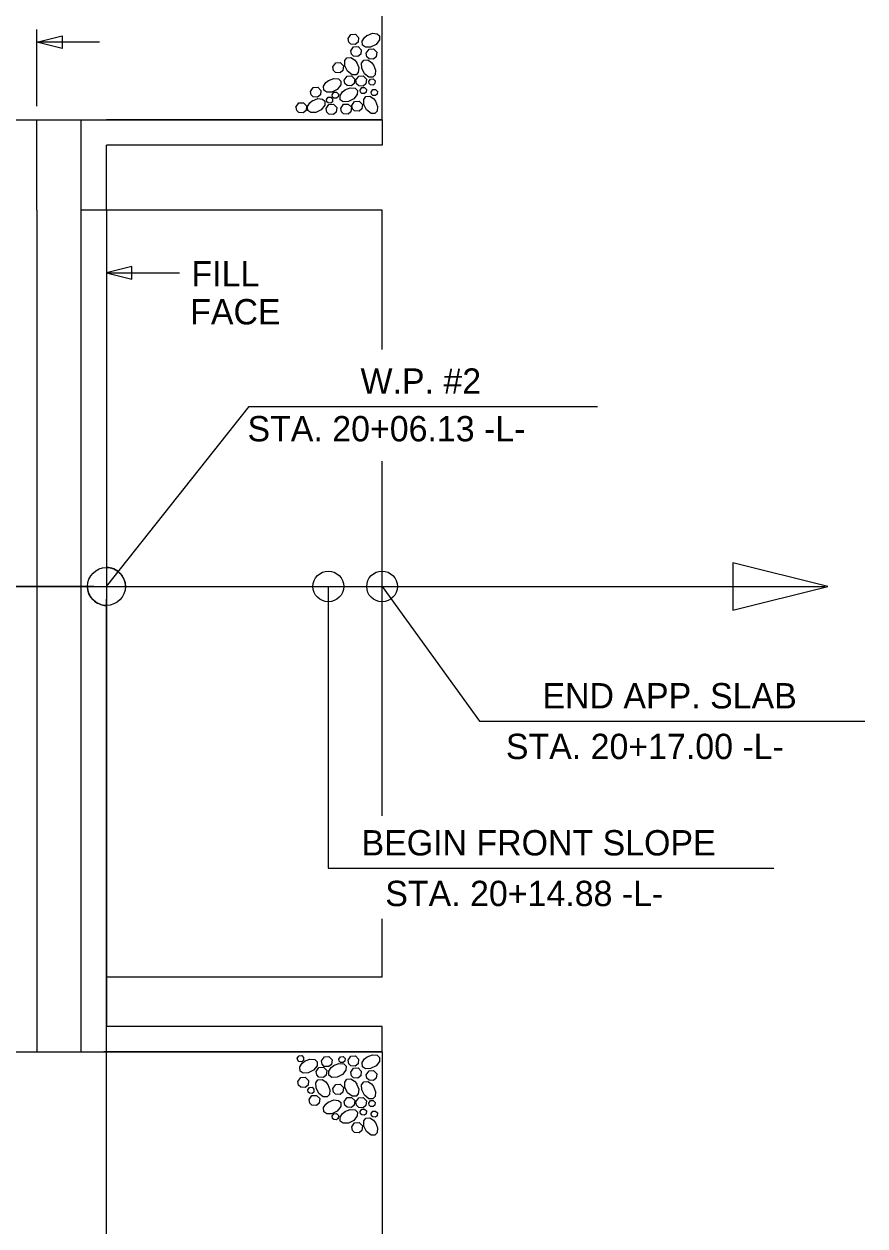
# Model space of a CAD drawing. Extents: x 985 to 1514, y -701 to -21.
# Drawn here: x 1154 to 1187.17, y -184.23 to -136.79 of the extents above; entities that cross this region are included whole.
import ezdxf

# ---------------------------------------------------------------- set-up
doc = ezdxf.new("R2010")
doc.units = 0
for name, color, linetype in [('Arrowhead Terminators CELL', 7, 'Continuous'), ('Auto Dimensioning', 7, 'Continuous'), ('Default', 7, 'Continuous'), ('Dimension Lines', 7, 'Continuous'), ('Mis -L- Lines', 7, 'Continuous'), ('Mis Object Lines', 7, 'Continuous'), ('Mis Object Lines Hidden', 7, 'Continuous'), ('Mis Work Point CELL', 7, 'Continuous'), ('Miscellaneous Lines CELL', 7, 'Continuous'), ('Sub End Bent Cap Lines CELL', 7, 'Continuous'), ('Sup Concrete Girder Lines', 7, 'Continuous'), ('Text', 7, 'Continuous'), ('User Information Notes', 7, 'Continuous')]:
    doc.layers.add(name, color=color, linetype=linetype)

# ---------------------------------------------------------------- blocks, each defined once
blk = doc.blocks.new('AH')
at = {"layer": 'Sub End Bent Cap Lines CELL'}
blk.add_lwpolyline([(0, 0), (-1.25, 0.312), (-1.25, -0.312)], close=True, dxfattribs=at)

msp = doc.modelspace()

# ---------------------------------------------------------------- linework, layer by layer
at = {"layer": 'Arrowhead Terminators CELL'}
for points in [[(1157.252, -146.603), (1158.252, -146.853), (1158.252, -146.353)], [(1185.71, -158.986), (1181.96, -158.048), (1181.96, -159.923)]]:
    msp.add_lwpolyline(points, close=True, dxfattribs=at)
at = {"layer": 'Auto Dimensioning'}
for p, q in [((1156.752, -158.986), (1143.03, -158.986)), ((1157.234, -159.486), (1157.234, -191.32))]:
    msp.add_line(p, q, dxfattribs=at)
at = {"layer": 'Default'}
msp.add_line((1157.142, -177.358), (1167.142, -177.358), dxfattribs=at)
at = {"layer": 'Dimension Lines'}
for p, q in [((1154.502, -140.029), (1154.502, -137.01)), ((1156.983, -137.51), (1154.502, -137.51)), ((1157.252, -146.603), (1160.13, -146.603)), ((1157.252, -158.986), (1162.882, -151.881)), ((1162.882, -151.881), (1176.615, -151.881)), ((1166.002, -158.986), (1166.002, -170.103)), ((1168.122, -158.986), (1171.966, -164.3)), ((1171.966, -164.3), (1187.167, -164.3)), ((1166.002, -170.103), (1183.575, -170.103))]:
    msp.add_line(p, q, dxfattribs=at)
for centre in [(1166.002, -158.986), (1168.122, -158.986)]:
    msp.add_circle(centre, 0.606, dxfattribs=at)
at = {"layer": 'Mis -L- Lines'}
msp.add_line((1058.329, -158.986), (1185.585, -158.986), dxfattribs=at)
at = {"layer": 'Mis Object Lines'}
for p, q in [((1153.502, -140.569), (1168.122, -140.569)), ((1154.502, -144.132), (1154.502, -140.569)), ((1156.252, -177.358), (1156.252, -140.569)), ((1168.122, -140.569), (1168.122, -141.569)), ((1168.122, -141.569), (1157.252, -141.569)), ((1157.252, -144.132), (1157.252, -141.569)), ((1154.502, -144.132), (1154.502, -177.358)), ((1168.122, -144.132), (1156.252, -144.132)), ((1168.122, -149.633), (1168.122, -144.132)), ((1168.122, -168.045), (1168.122, -154.044)), ((1168.122, -174.402), (1168.122, -172.099)), ((1168.122, -174.402), (1157.252, -174.402)), ((1157.252, -174.402), (1157.252, -176.358)), ((1168.122, -176.358), (1157.252, -176.358)), ((1168.122, -177.358), (1168.122, -176.358)), ((1153.502, -177.358), (1168.122, -177.358))]:
    msp.add_line(p, q, dxfattribs=at)
at = {"layer": 'Mis Object Lines Hidden'}
msp.add_line((1157.252, -144.132), (1157.252, -174.965), dxfattribs=at)
at = {"layer": 'Mis Work Point CELL'}
for p, q in [((1157.252, -158.236), (1157.252, -158.986)), ((1156.502, -158.986), (1157.252, -158.986)), ((1157.252, -158.986), (1157.252, -159.736)), ((1157.252, -158.986), (1158.002, -158.986)), ((1158.002, -158.986), (1158.002, -158.986)), ((1157.252, -159.736), (1157.252, -159.736))]:
    msp.add_line(p, q, dxfattribs=at)
msp.add_circle((1157.252, -158.986), 0.75, dxfattribs=at)
for start, end in [(359.997, 89.9989), (180.0011, 270.003)]:
    msp.add_arc((1157.252, -158.986), 0.75, start, end, dxfattribs=at)
at = {"layer": 'Miscellaneous Lines CELL'}
for points in [[(1166.78, -137.366), (1166.892, -137.207), (1167.071, -137.196), (1167.195, -137.325), (1167.177, -137.506), (1167.067, -137.598), (1166.89, -137.585), (1166.807, -137.505), (1166.78, -137.366)], [(1167.532, -137.239), (1167.741, -137.156), (1167.934, -137.172), (1168.025, -137.259), (1168.022, -137.415), (1167.884, -137.593), (1167.669, -137.7), (1167.467, -137.704), (1167.353, -137.623), (1167.342, -137.462), (1167.434, -137.318), (1167.54, -137.233)], [(1166.885, -137.843), (1166.997, -137.684), (1167.176, -137.674), (1167.301, -137.803), (1167.283, -137.983), (1167.172, -138.075), (1166.995, -138.062), (1166.912, -137.982), (1166.885, -137.843)], [(1167.498, -137.941), (1167.61, -137.781), (1167.789, -137.771), (1167.913, -137.9), (1167.895, -138.081), (1167.785, -138.173), (1167.608, -138.16), (1167.525, -138.079), (1167.498, -137.941)], [(1166.181, -138.483), (1166.293, -138.324), (1166.472, -138.313), (1166.596, -138.442), (1166.578, -138.623), (1166.468, -138.715), (1166.291, -138.702), (1166.208, -138.622), (1166.181, -138.483)], [(1167.118, -138.297), (1167.201, -138.507), (1167.185, -138.699), (1167.098, -138.791), (1166.942, -138.788), (1166.764, -138.649), (1166.657, -138.434), (1166.653, -138.232), (1166.734, -138.118), (1166.895, -138.108), (1167.039, -138.2), (1167.124, -138.306)], [(1167.783, -138.399), (1167.866, -138.609), (1167.849, -138.801), (1167.762, -138.893), (1167.606, -138.89), (1167.428, -138.751), (1167.321, -138.536), (1167.317, -138.334), (1167.398, -138.22), (1167.56, -138.209), (1167.704, -138.302), (1167.788, -138.407)], [(1166.004, -139.017), (1166.214, -138.934), (1166.406, -138.951), (1166.498, -139.038), (1166.495, -139.194), (1166.356, -139.371), (1166.142, -139.479), (1165.939, -139.482), (1165.825, -139.401), (1165.815, -139.24), (1165.907, -139.096), (1166.013, -139.012)], [(1166.629, -139.003), (1166.741, -138.843), (1166.92, -138.833), (1167.045, -138.962), (1167.027, -139.143), (1166.916, -139.234), (1166.739, -139.222), (1166.656, -139.141), (1166.629, -139.003)], [(1167.09, -139.009), (1167.202, -138.85), (1167.381, -138.84), (1167.506, -138.969), (1167.488, -139.149), (1167.377, -139.241), (1167.2, -139.228), (1167.117, -139.148), (1167.09, -139.009)], [(1167.6, -139.059), (1167.667, -138.963), (1167.775, -138.957), (1167.849, -139.034), (1167.838, -139.143), (1167.772, -139.198), (1167.666, -139.19), (1167.616, -139.142), (1167.6, -139.059)], [(1165.295, -139.448), (1165.407, -139.289), (1165.586, -139.278), (1165.711, -139.407), (1165.693, -139.588), (1165.582, -139.68), (1165.405, -139.667), (1165.322, -139.587), (1165.295, -139.448)], [(1166.655, -139.392), (1166.864, -139.308), (1167.057, -139.325), (1167.148, -139.412), (1167.145, -139.568), (1167.006, -139.746), (1166.792, -139.853), (1166.59, -139.857), (1166.476, -139.776), (1166.465, -139.615), (1166.557, -139.471), (1166.663, -139.386)], [(1167.253, -139.395), (1167.32, -139.299), (1167.428, -139.293), (1167.502, -139.37), (1167.492, -139.479), (1167.425, -139.534), (1167.319, -139.526), (1167.269, -139.478), (1167.253, -139.395)], [(1167.695, -139.474), (1167.762, -139.378), (1167.869, -139.372), (1167.944, -139.449), (1167.933, -139.558), (1167.867, -139.613), (1167.761, -139.605), (1167.711, -139.557), (1167.695, -139.474)], [(1164.727, -140.064), (1164.84, -139.905), (1165.018, -139.895), (1165.143, -140.024), (1165.125, -140.204), (1165.014, -140.296), (1164.838, -140.283), (1164.755, -140.203), (1164.728, -140.064)], [(1165.374, -139.819), (1165.583, -139.735), (1165.776, -139.752), (1165.867, -139.839), (1165.864, -139.995), (1165.726, -140.173), (1165.511, -140.28), (1165.309, -140.284), (1165.195, -140.203), (1165.184, -140.042), (1165.276, -139.898), (1165.382, -139.813)], [(1165.924, -139.773), (1165.991, -139.677), (1166.099, -139.671), (1166.173, -139.749), (1166.162, -139.857), (1166.096, -139.912), (1165.99, -139.905), (1165.94, -139.856), (1165.924, -139.773)], [(1166.155, -139.579), (1166.222, -139.483), (1166.33, -139.477), (1166.404, -139.554), (1166.394, -139.663), (1166.327, -139.718), (1166.221, -139.71), (1166.171, -139.662), (1166.155, -139.579)], [(1166.929, -140), (1167.041, -139.841), (1167.22, -139.83), (1167.344, -139.959), (1167.326, -140.14), (1167.216, -140.232), (1167.039, -140.219), (1166.956, -140.138), (1166.929, -140)], [(1167.864, -139.829), (1167.947, -140.039), (1167.93, -140.231), (1167.843, -140.323), (1167.687, -140.32), (1167.51, -140.181), (1167.402, -139.966), (1167.399, -139.764), (1167.48, -139.65), (1167.641, -139.639), (1167.785, -139.732), (1167.869, -139.838)], [(1165.917, -140.123), (1166.029, -139.964), (1166.207, -139.954), (1166.332, -140.083), (1166.314, -140.263), (1166.203, -140.355), (1166.027, -140.343), (1165.944, -140.262), (1165.917, -140.123)], [(1166.495, -140.117), (1166.607, -139.957), (1166.786, -139.947), (1166.91, -140.076), (1166.892, -140.257), (1166.781, -140.349), (1166.605, -140.336), (1166.522, -140.255), (1166.495, -140.117)], [(1164.778, -177.605), (1164.846, -177.509), (1164.953, -177.503), (1165.028, -177.581), (1165.017, -177.689), (1164.951, -177.744), (1164.845, -177.736), (1164.795, -177.688), (1164.779, -177.605)], [(1164.778, -177.605), (1164.846, -177.509), (1164.953, -177.503), (1165.028, -177.581), (1165.017, -177.689), (1164.951, -177.744), (1164.845, -177.736), (1164.795, -177.688), (1164.779, -177.605)], [(1165.069, -177.728), (1165.278, -177.645), (1165.471, -177.661), (1165.562, -177.748), (1165.56, -177.904), (1165.421, -178.082), (1165.206, -178.189), (1165.004, -178.193), (1164.89, -178.112), (1164.879, -177.951), (1164.971, -177.807), (1165.077, -177.722)], [(1165.069, -177.728), (1165.278, -177.645), (1165.471, -177.661), (1165.562, -177.748), (1165.56, -177.904), (1165.421, -178.082), (1165.206, -178.189), (1165.004, -178.193), (1164.89, -178.112), (1164.879, -177.951), (1164.971, -177.807), (1165.077, -177.722)], [(1165.733, -177.707), (1165.845, -177.548), (1166.024, -177.538), (1166.148, -177.667), (1166.13, -177.847), (1166.019, -177.939), (1165.843, -177.926), (1165.76, -177.846), (1165.733, -177.707)], [(1165.733, -177.707), (1165.845, -177.548), (1166.024, -177.538), (1166.148, -177.667), (1166.13, -177.847), (1166.019, -177.939), (1165.843, -177.926), (1165.76, -177.846), (1165.733, -177.707)], [(1166.208, -177.897), (1166.417, -177.814), (1166.61, -177.831), (1166.701, -177.918), (1166.698, -178.074), (1166.559, -178.252), (1166.345, -178.359), (1166.142, -178.362), (1166.029, -178.281), (1166.018, -178.12), (1166.11, -177.976), (1166.216, -177.892)], [(1166.208, -177.897), (1166.417, -177.814), (1166.61, -177.831), (1166.701, -177.918), (1166.698, -178.074), (1166.559, -178.252), (1166.345, -178.359), (1166.142, -178.362), (1166.029, -178.281), (1166.018, -178.12), (1166.11, -177.976), (1166.216, -177.892)], [(1166.412, -177.642), (1166.48, -177.546), (1166.587, -177.54), (1166.662, -177.617), (1166.651, -177.726), (1166.585, -177.781), (1166.479, -177.773), (1166.429, -177.725), (1166.413, -177.642)], [(1166.412, -177.642), (1166.48, -177.546), (1166.587, -177.54), (1166.662, -177.617), (1166.651, -177.726), (1166.585, -177.781), (1166.479, -177.773), (1166.429, -177.725), (1166.413, -177.642)], [(1166.78, -177.683), (1166.892, -177.524), (1167.071, -177.513), (1167.195, -177.642), (1167.177, -177.823), (1167.066, -177.915), (1166.89, -177.902), (1166.807, -177.822), (1166.78, -177.683)], [(1166.78, -177.683), (1166.892, -177.524), (1167.071, -177.513), (1167.195, -177.642), (1167.177, -177.823), (1167.066, -177.915), (1166.89, -177.902), (1166.807, -177.822), (1166.78, -177.683)], [(1167.532, -177.556), (1167.741, -177.473), (1167.934, -177.489), (1168.025, -177.576), (1168.022, -177.732), (1167.883, -177.91), (1167.669, -178.017), (1167.467, -178.021), (1167.353, -177.94), (1167.342, -177.779), (1167.434, -177.635), (1167.54, -177.55)], [(1167.532, -177.556), (1167.741, -177.473), (1167.934, -177.489), (1168.025, -177.576), (1168.022, -177.732), (1167.883, -177.91), (1167.669, -178.017), (1167.467, -178.021), (1167.353, -177.94), (1167.342, -177.779), (1167.434, -177.635), (1167.54, -177.55)], [(1164.803, -178.529), (1164.915, -178.369), (1165.094, -178.359), (1165.219, -178.488), (1165.201, -178.669), (1165.09, -178.761), (1164.913, -178.748), (1164.83, -178.667), (1164.803, -178.529)], [(1164.803, -178.529), (1164.915, -178.369), (1165.094, -178.359), (1165.219, -178.488), (1165.201, -178.669), (1165.09, -178.761), (1164.913, -178.748), (1164.83, -178.667), (1164.803, -178.529)], [(1165.522, -178.129), (1165.634, -177.97), (1165.813, -177.959), (1165.937, -178.088), (1165.919, -178.269), (1165.809, -178.361), (1165.632, -178.348), (1165.549, -178.267), (1165.522, -178.129)], [(1165.522, -178.129), (1165.634, -177.97), (1165.813, -177.959), (1165.937, -178.088), (1165.919, -178.269), (1165.809, -178.361), (1165.632, -178.348), (1165.549, -178.267), (1165.522, -178.129)], [(1166.885, -178.16), (1166.997, -178.001), (1167.176, -177.991), (1167.3, -178.12), (1167.282, -178.3), (1167.172, -178.392), (1166.995, -178.379), (1166.912, -178.299), (1166.885, -178.16)], [(1166.885, -178.16), (1166.997, -178.001), (1167.176, -177.991), (1167.3, -178.12), (1167.282, -178.3), (1167.172, -178.392), (1166.995, -178.379), (1166.912, -178.299), (1166.885, -178.16)], [(1167.498, -178.258), (1167.61, -178.098), (1167.789, -178.088), (1167.913, -178.217), (1167.895, -178.398), (1167.785, -178.49), (1167.608, -178.477), (1167.525, -178.396), (1167.498, -178.258)], [(1167.498, -178.258), (1167.61, -178.098), (1167.789, -178.088), (1167.913, -178.217), (1167.895, -178.398), (1167.785, -178.49), (1167.608, -178.477), (1167.525, -178.396), (1167.498, -178.258)], [(1165.188, -178.855), (1165.256, -178.76), (1165.363, -178.754), (1165.437, -178.831), (1165.427, -178.939), (1165.36, -178.995), (1165.254, -178.987), (1165.205, -178.939), (1165.188, -178.855)], [(1165.188, -178.855), (1165.256, -178.76), (1165.363, -178.754), (1165.437, -178.831), (1165.427, -178.939), (1165.36, -178.995), (1165.254, -178.987), (1165.205, -178.939), (1165.188, -178.855)], [(1165.98, -178.641), (1166.063, -178.851), (1166.046, -179.044), (1165.959, -179.135), (1165.803, -179.132), (1165.625, -178.993), (1165.518, -178.779), (1165.514, -178.576), (1165.595, -178.462), (1165.756, -178.452), (1165.9, -178.544), (1165.985, -178.65)], [(1165.98, -178.641), (1166.063, -178.851), (1166.046, -179.044), (1165.959, -179.135), (1165.803, -179.132), (1165.625, -178.993), (1165.518, -178.779), (1165.514, -178.576), (1165.595, -178.462), (1165.756, -178.452), (1165.9, -178.544), (1165.985, -178.65)], [(1166.181, -178.8), (1166.293, -178.641), (1166.472, -178.63), (1166.596, -178.759), (1166.578, -178.94), (1166.468, -179.032), (1166.291, -179.019), (1166.208, -178.939), (1166.181, -178.8)], [(1166.181, -178.8), (1166.293, -178.641), (1166.472, -178.63), (1166.596, -178.759), (1166.578, -178.94), (1166.468, -179.032), (1166.291, -179.019), (1166.208, -178.939), (1166.181, -178.8)], [(1167.118, -178.614), (1167.201, -178.824), (1167.185, -179.016), (1167.098, -179.108), (1166.942, -179.105), (1166.764, -178.966), (1166.657, -178.752), (1166.653, -178.549), (1166.734, -178.435), (1166.895, -178.425), (1167.039, -178.517), (1167.124, -178.623)], [(1167.118, -178.614), (1167.201, -178.824), (1167.185, -179.016), (1167.098, -179.108), (1166.942, -179.105), (1166.764, -178.966), (1166.657, -178.752), (1166.653, -178.549), (1166.734, -178.435), (1166.895, -178.425), (1167.039, -178.517), (1167.124, -178.623)], [(1167.783, -178.716), (1167.866, -178.926), (1167.849, -179.118), (1167.762, -179.21), (1167.606, -179.207), (1167.428, -179.068), (1167.321, -178.853), (1167.317, -178.651), (1167.398, -178.537), (1167.559, -178.526), (1167.704, -178.619), (1167.788, -178.724)], [(1167.783, -178.716), (1167.866, -178.926), (1167.849, -179.118), (1167.762, -179.21), (1167.606, -179.207), (1167.428, -179.068), (1167.321, -178.853), (1167.317, -178.651), (1167.398, -178.537), (1167.559, -178.526), (1167.704, -178.619), (1167.788, -178.724)], [(1165.245, -179.241), (1165.357, -179.081), (1165.536, -179.071), (1165.661, -179.2), (1165.643, -179.381), (1165.532, -179.473), (1165.356, -179.46), (1165.272, -179.379), (1165.245, -179.241)], [(1165.245, -179.241), (1165.357, -179.081), (1165.536, -179.071), (1165.661, -179.2), (1165.643, -179.381), (1165.532, -179.473), (1165.356, -179.46), (1165.272, -179.379), (1165.245, -179.241)], [(1166.004, -179.334), (1166.214, -179.251), (1166.406, -179.268), (1166.498, -179.355), (1166.495, -179.511), (1166.356, -179.689), (1166.141, -179.796), (1165.939, -179.799), (1165.825, -179.718), (1165.814, -179.557), (1165.907, -179.413), (1166.013, -179.329)], [(1166.004, -179.334), (1166.214, -179.251), (1166.406, -179.268), (1166.498, -179.355), (1166.495, -179.511), (1166.356, -179.689), (1166.141, -179.796), (1165.939, -179.799), (1165.825, -179.718), (1165.814, -179.557), (1165.907, -179.413), (1166.013, -179.329)], [(1166.629, -179.32), (1166.741, -179.16), (1166.92, -179.15), (1167.045, -179.279), (1167.027, -179.46), (1166.916, -179.552), (1166.739, -179.539), (1166.656, -179.458), (1166.629, -179.32)], [(1166.629, -179.32), (1166.741, -179.16), (1166.92, -179.15), (1167.045, -179.279), (1167.027, -179.46), (1166.916, -179.552), (1166.739, -179.539), (1166.656, -179.458), (1166.629, -179.32)], [(1167.09, -179.326), (1167.202, -179.167), (1167.381, -179.157), (1167.505, -179.286), (1167.487, -179.466), (1167.377, -179.558), (1167.2, -179.545), (1167.117, -179.465), (1167.09, -179.326)], [(1167.09, -179.326), (1167.202, -179.167), (1167.381, -179.157), (1167.505, -179.286), (1167.487, -179.466), (1167.377, -179.558), (1167.2, -179.545), (1167.117, -179.465), (1167.09, -179.326)], [(1167.6, -179.376), (1167.667, -179.28), (1167.775, -179.274), (1167.849, -179.351), (1167.838, -179.46), (1167.772, -179.515), (1167.666, -179.507), (1167.616, -179.459), (1167.6, -179.376)], [(1167.6, -179.376), (1167.667, -179.28), (1167.775, -179.274), (1167.849, -179.351), (1167.838, -179.46), (1167.772, -179.515), (1167.666, -179.507), (1167.616, -179.459), (1167.6, -179.376)], [(1166.655, -179.709), (1166.864, -179.626), (1167.057, -179.642), (1167.148, -179.729), (1167.145, -179.885), (1167.006, -180.063), (1166.792, -180.17), (1166.589, -180.174), (1166.476, -180.093), (1166.465, -179.932), (1166.557, -179.788), (1166.663, -179.703)], [(1166.655, -179.709), (1166.864, -179.626), (1167.057, -179.642), (1167.148, -179.729), (1167.145, -179.885), (1167.006, -180.063), (1166.792, -180.17), (1166.589, -180.174), (1166.476, -180.093), (1166.465, -179.932), (1166.557, -179.788), (1166.663, -179.703)], [(1167.253, -179.712), (1167.32, -179.616), (1167.428, -179.61), (1167.502, -179.687), (1167.492, -179.796), (1167.425, -179.851), (1167.319, -179.843), (1167.269, -179.795), (1167.253, -179.712)], [(1167.253, -179.712), (1167.32, -179.616), (1167.428, -179.61), (1167.502, -179.687), (1167.492, -179.796), (1167.425, -179.851), (1167.319, -179.843), (1167.269, -179.795), (1167.253, -179.712)], [(1167.695, -179.791), (1167.762, -179.695), (1167.869, -179.689), (1167.944, -179.766), (1167.933, -179.875), (1167.867, -179.93), (1167.761, -179.922), (1167.711, -179.874), (1167.695, -179.791)], [(1167.695, -179.791), (1167.762, -179.695), (1167.869, -179.689), (1167.944, -179.766), (1167.933, -179.875), (1167.867, -179.93), (1167.761, -179.922), (1167.711, -179.874), (1167.695, -179.791)], [(1166.155, -179.896), (1166.222, -179.8), (1166.33, -179.794), (1166.404, -179.871), (1166.393, -179.98), (1166.327, -180.035), (1166.221, -180.027), (1166.171, -179.979), (1166.155, -179.896)], [(1166.155, -179.896), (1166.222, -179.8), (1166.33, -179.794), (1166.404, -179.871), (1166.393, -179.98), (1166.327, -180.035), (1166.221, -180.027), (1166.171, -179.979), (1166.155, -179.896)], [(1166.929, -180.317), (1167.041, -180.158), (1167.22, -180.147), (1167.344, -180.276), (1167.326, -180.457), (1167.216, -180.549), (1167.039, -180.536), (1166.956, -180.455), (1166.929, -180.317)], [(1166.929, -180.317), (1167.041, -180.158), (1167.22, -180.147), (1167.344, -180.276), (1167.326, -180.457), (1167.216, -180.549), (1167.039, -180.536), (1166.956, -180.455), (1166.929, -180.317)], [(1167.864, -180.146), (1167.947, -180.356), (1167.93, -180.548), (1167.843, -180.64), (1167.687, -180.637), (1167.51, -180.498), (1167.402, -180.283), (1167.399, -180.081), (1167.48, -179.967), (1167.641, -179.956), (1167.785, -180.049), (1167.869, -180.155)], [(1167.864, -180.146), (1167.947, -180.356), (1167.93, -180.548), (1167.843, -180.64), (1167.687, -180.637), (1167.51, -180.498), (1167.402, -180.283), (1167.399, -180.081), (1167.48, -179.967), (1167.641, -179.956), (1167.785, -180.049), (1167.869, -180.155)]]:
    msp.add_lwpolyline(points, dxfattribs=at)
at = {"layer": 'Sup Concrete Girder Lines'}
for p, q in [((1168.122, -140.593), (1168.122, -124.768)), ((1168.122, -140.569), (1157.252, -140.569)), ((1168.142, -177.358), (1157.142, -177.358)), ((1168.122, -177.358), (1168.122, -197.986))]:
    msp.add_line(p, q, dxfattribs=at)
msp.add_arc((1169.597, -175.48), 22.747, 184.9278, 261.7748, dxfattribs=at)
at = {"layer": 'User Information Notes'}
msp.add_line((1157.252, -158.986), (1157.252, -158.986), dxfattribs=at)
msp.add_line((1157.252, -158.986), (1157.252, -158.986), dxfattribs=at)

# ---------------------------------------------------------------- block references
at = {"layer": 'Arrowhead Terminators CELL', "xscale": 0.8, "yscale": -0.8000000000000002, "rotation": 180}
msp.add_blockref('AH', (1154.502, -137.51), dxfattribs=at)

# ---------------------------------------------------------------- texts
at = {"layer": 'Dimension Lines'}
for s, p in [('FILL', (1160.605, -147.144)), ('FACE', (1160.554, -148.644))]:
    msp.add_text(s, height=1, dxfattribs=at).set_placement(p)
at = {"layer": 'Text'}
for s, p in [('W.P. #2', (1167.272, -151.381)), ('STA. 20+06.13 -L-', (1162.814, -153.26)), ('END APP. SLAB', (1174.446, -163.8)), ('STA. 20+17.00 -L-', (1173.005, -165.8)), ('BEGIN FRONT SLOPE', (1167.31, -169.603)), ('STA. 20+14.88 -L-', (1168.249, -171.603))]:
    msp.add_text(s, height=1, dxfattribs=at).set_placement(p)

doc.saveas('drawing.dxf')
